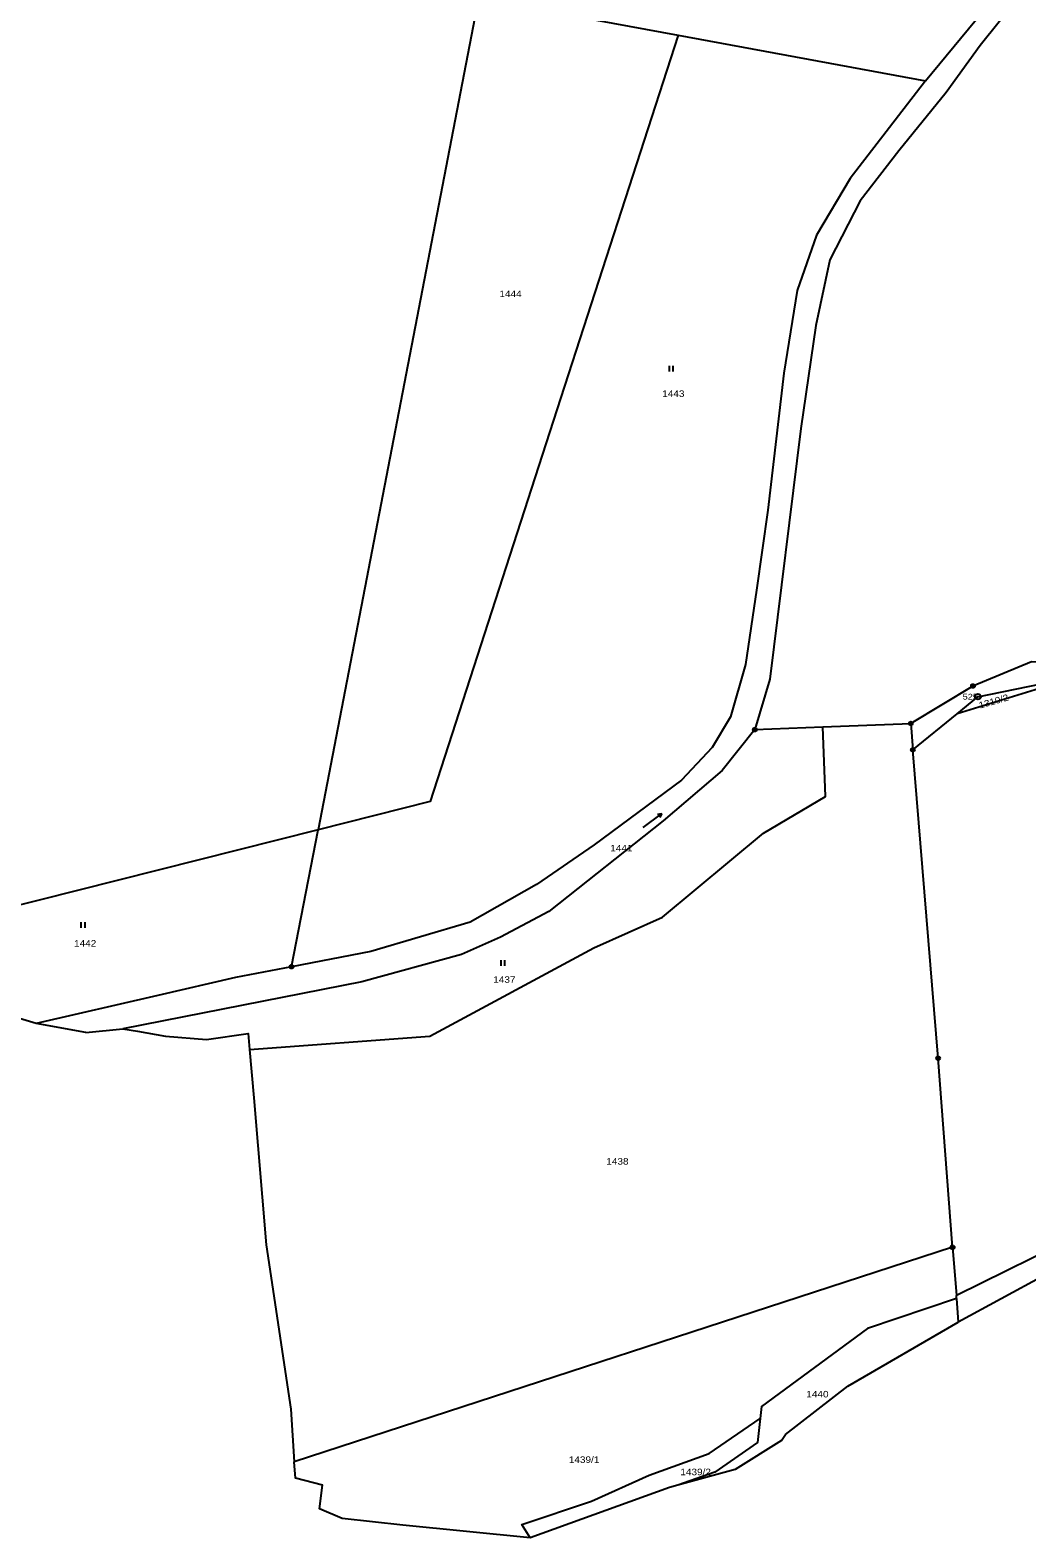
# Model space of a CAD drawing. Extents: x -872229 to -869198, y -1075981 to -1074329.
# Drawn here: x -870892.8 to -870632.3, y -1075980.9 to -1075586.7 of the extents above; entities that cross this region are included whole.
import ezdxf
from ezdxf.enums import TextEntityAlignment as Align

# ---------------------------------------------------------------- set-up
doc = ezdxf.new("R2010")
doc.units = 0
doc.header["$LTSCALE"] = 0.68
for name, color, linetype, lineweight in [('1', 7, 'Continuous', 25), ('3', 7, 'Continuous', 25), ('8', 7, 'Continuous', 25)]:
    doc.layers.add(name, color=color, linetype=linetype, lineweight=lineweight)
doc.layers.add('2', color=7, linetype='Continuous')

msp = doc.modelspace()

# ---------------------------------------------------------------- linework, layer by layer
at = {"layer": '1'}
for p, q in [((-870618.4, -1075755.49), (-870650.51, -1075765.39)), ((-870878.19, -1075848.76), (-870891.16, -1075846.37)), ((-870878.19, -1075848.76), (-870868.54, -1075847.76)), ((-870835.43, -1075853.18), (-870834.35, -1075865.8)), ((-870651.69, -1075904.9), (-870823.75, -1075960.94)), ((-870651.69, -1075904.9), (-870650.72, -1075917.52)), ((-870650.66, -1075918.25), (-870650.72, -1075917.52)), ((-870650.66, -1075918.25), (-870650.23, -1075924.48)), ((-870713.83, -1075963.64), (-870723.53, -1075967.1)), ((-870795.41, -1075977.55), (-870811.25, -1075975.79))]:
    msp.add_line(p, q, dxfattribs=at)
for points in [[(-870769.48, -1075546.88), (-870775.56, -1075578.36), (-870723.44, -1075587.98), (-870658.76, -1075599.92), (-870633.02, -1075568.68)], [(-870775.56, -1075578.36), (-870796.43, -1075686.4), (-870817.54, -1075795.72)], [(-870634.57, -1075578.24), (-870644.53, -1075590.75), (-870653.4, -1075603.02), (-870665.74, -1075618.29), (-870675.84, -1075631.34), (-870683.76, -1075646.76), (-870687.46, -1075663.9), (-870691.39, -1075690.84), (-870699.49, -1075756.36), (-870703.4, -1075769.57), (-870685.61, -1075768.87), (-870662.6, -1075767.96)], [(-870723.44, -1075587.98), (-870756.06, -1075688.89), (-870788.21, -1075788.31), (-870817.54, -1075795.72)], [(-870497.88, -1075584.92), (-870501.24, -1075597.99), (-870508.17, -1075703.33), (-870541.87, -1075736.74), (-870558.64, -1075743.46), (-870618.91, -1075752.53), (-870631.08, -1075751.8), (-870646.39, -1075758.16), (-870662.6, -1075767.96)], [(-870658.76, -1075599.92), (-870678.46, -1075625.49), (-870687.24, -1075640.3), (-870692.36, -1075654.75), (-870695.8, -1075676.34), (-870699.97, -1075712.19), (-870702.99, -1075733.08), (-870705.81, -1075752.56), (-870709.71, -1075766.23), (-870714.5, -1075774.23), (-870722.58, -1075782.75), (-870745.39, -1075799.68), (-870760.4, -1075810.04), (-870777.81, -1075819.9), (-870803.76, -1075827.6), (-870824.46, -1075831.55), (-870817.54, -1075795.72), (-870984.88, -1075837.95)], [(-870650.51, -1075765.39), (-870645.07, -1075760.95), (-870618.4, -1075755.49), (-870560.25, -1075746.77), (-870557.85, -1075746.37)], [(-870662.6, -1075767.96), (-870662.1, -1075774.86), (-870650.51, -1075765.39)], [(-870835.43, -1075853.18), (-870788.29, -1075849.73), (-870745.46, -1075826.63), (-870727.54, -1075818.59), (-870701.15, -1075796.59), (-870684.9, -1075787.01), (-870685.61, -1075768.87)], [(-870703.4, -1075769.57), (-870711.89, -1075780.25), (-870727.3, -1075793.42), (-870757.25, -1075817.1), (-870769.85, -1075823.85), (-870780.02, -1075828.35), (-870806.1, -1075835.5), (-870868.54, -1075847.76)], [(-870651.69, -1075904.9), (-870655.48, -1075855.47), (-870662.1, -1075774.86)], [(-870824.46, -1075831.55), (-870839.13, -1075834.34), (-870859.41, -1075839.03), (-870891.16, -1075846.37)], [(-870891.16, -1075846.37), (-870900.85, -1075843.51), (-870915.96, -1075844.76), (-870940.05, -1075843.27), (-870969.07, -1075840.28), (-870984.88, -1075837.95)], [(-870868.54, -1075847.76), (-870864.68, -1075848.42), (-870857.37, -1075849.66), (-870846.7, -1075850.59), (-870835.79, -1075848.98), (-870835.43, -1075853.18)], [(-870549.14, -1075861.93), (-870617.86, -1075901.31), (-870650.72, -1075917.52)], [(-870834.35, -1075865.8), (-870831.07, -1075904.26), (-870824.66, -1075947.17), (-870823.75, -1075960.94)], [(-870546.66, -1075871.21), (-870616.52, -1075906.2), (-870650.23, -1075924.48)], [(-870650.66, -1075918.25), (-870673.9, -1075926.14), (-870701.61, -1075946.51), (-870701.96, -1075949.68)], [(-870696.44, -1075955.38), (-870695.33, -1075953.82), (-870679.07, -1075941.16), (-870650.23, -1075924.48)], [(-870762.08, -1075980.85), (-870764.28, -1075977.33), (-870746.06, -1075971.25), (-870730.99, -1075964.47), (-870715.35, -1075958.8), (-870701.96, -1075949.68)], [(-870701.96, -1075949.68), (-870702.66, -1075955.95), (-870713.83, -1075963.64)], [(-870696.44, -1075955.38), (-870708.5, -1075963), (-870723.53, -1075967.1)], [(-870811.25, -1075975.79), (-870817.18, -1075973.25), (-870816.39, -1075967.05), (-870823.46, -1075965.24), (-870823.75, -1075960.94)], [(-870723.53, -1075967.1), (-870725.66, -1075967.68), (-870762.08, -1075980.85), (-870795.41, -1075977.55)]]:
    msp.add_lwpolyline(points, dxfattribs=at)
at = {"layer": '3'}
for p, q in [((-870725.691, -1075675.97), (-870725.691, -1075674.47)), ((-870724.69, -1075675.97), (-870724.69, -1075674.47)), ((-870727.735, -1075791.571), (-870728.214, -1075792.56)), ((-870879.401, -1075821.41), (-870879.401, -1075819.91)), ((-870878.4, -1075821.41), (-870878.4, -1075819.91)), ((-870769.711, -1075831.33), (-870769.711, -1075829.83)), ((-870768.71, -1075831.33), (-870768.71, -1075829.83))]:
    msp.add_line(p, q, dxfattribs=at)
msp.add_lwpolyline([(-870732.527, -1075795.182), (-870727.735, -1075791.571), (-870728.817, -1075791.759)], dxfattribs=at)
at = {"layer": '8'}
for centre, radius in [((-870646.39, -1075758.1599), 0.5), ((-870646.39, -1075758.1599), 0.0303), ((-870645.07, -1075760.9498), 0.75), ((-870645.07, -1075760.9498), 0.03), ((-870703.4, -1075769.5699), 0.5), ((-870662.6, -1075767.9599), 0.5), ((-870662.6, -1075767.9599), 0.0303), ((-870703.4, -1075769.5699), 0.0303), ((-870662.1, -1075774.8599), 0.5), ((-870662.1, -1075774.8599), 0.0303), ((-870824.46, -1075831.5499), 0.5), ((-870824.46, -1075831.5499), 0.0303), ((-870655.48, -1075855.4699), 0.5), ((-870655.48, -1075855.4699), 0.0303), ((-870651.69, -1075904.8999), 0.5), ((-870651.69, -1075904.8999), 0.0303)]:
    msp.add_circle(centre, radius, dxfattribs=at)

# ---------------------------------------------------------------- texts
at = {"layer": '2', "width": 1.15}
for s, p in [('1444', (-870770.13, -1075656.47)), ('1443', (-870727.59, -1075682.58)), ('1441', (-870741.17, -1075801.4)), ('1442', (-870881.29, -1075826.29)), ('1437', (-870771.75, -1075835.75)), ('1438', (-870742.2, -1075883.27)), ('1440', (-870689.93, -1075944.14))]:
    msp.add_text(s, height=1.7, dxfattribs=at).set_placement(p)
msp.add_text('1310/2', height=1.7, rotation=16, dxfattribs=at).set_placement((-870644.575, -1075764.067))
for s, p in [('1439/1', (-870748.009, -1075961.26)), ('1439/2', (-870718.849, -1075964.47))]:
    msp.add_text(s, height=1.7, dxfattribs=at).set_placement(p, align=Align.CENTER)
at = {"layer": '8', "width": 1.2}
msp.add_text('525', height=1.5, dxfattribs=at).set_placement((-870645.07, -1075761.7), align=Align.RIGHT)

doc.saveas('drawing.dxf')
